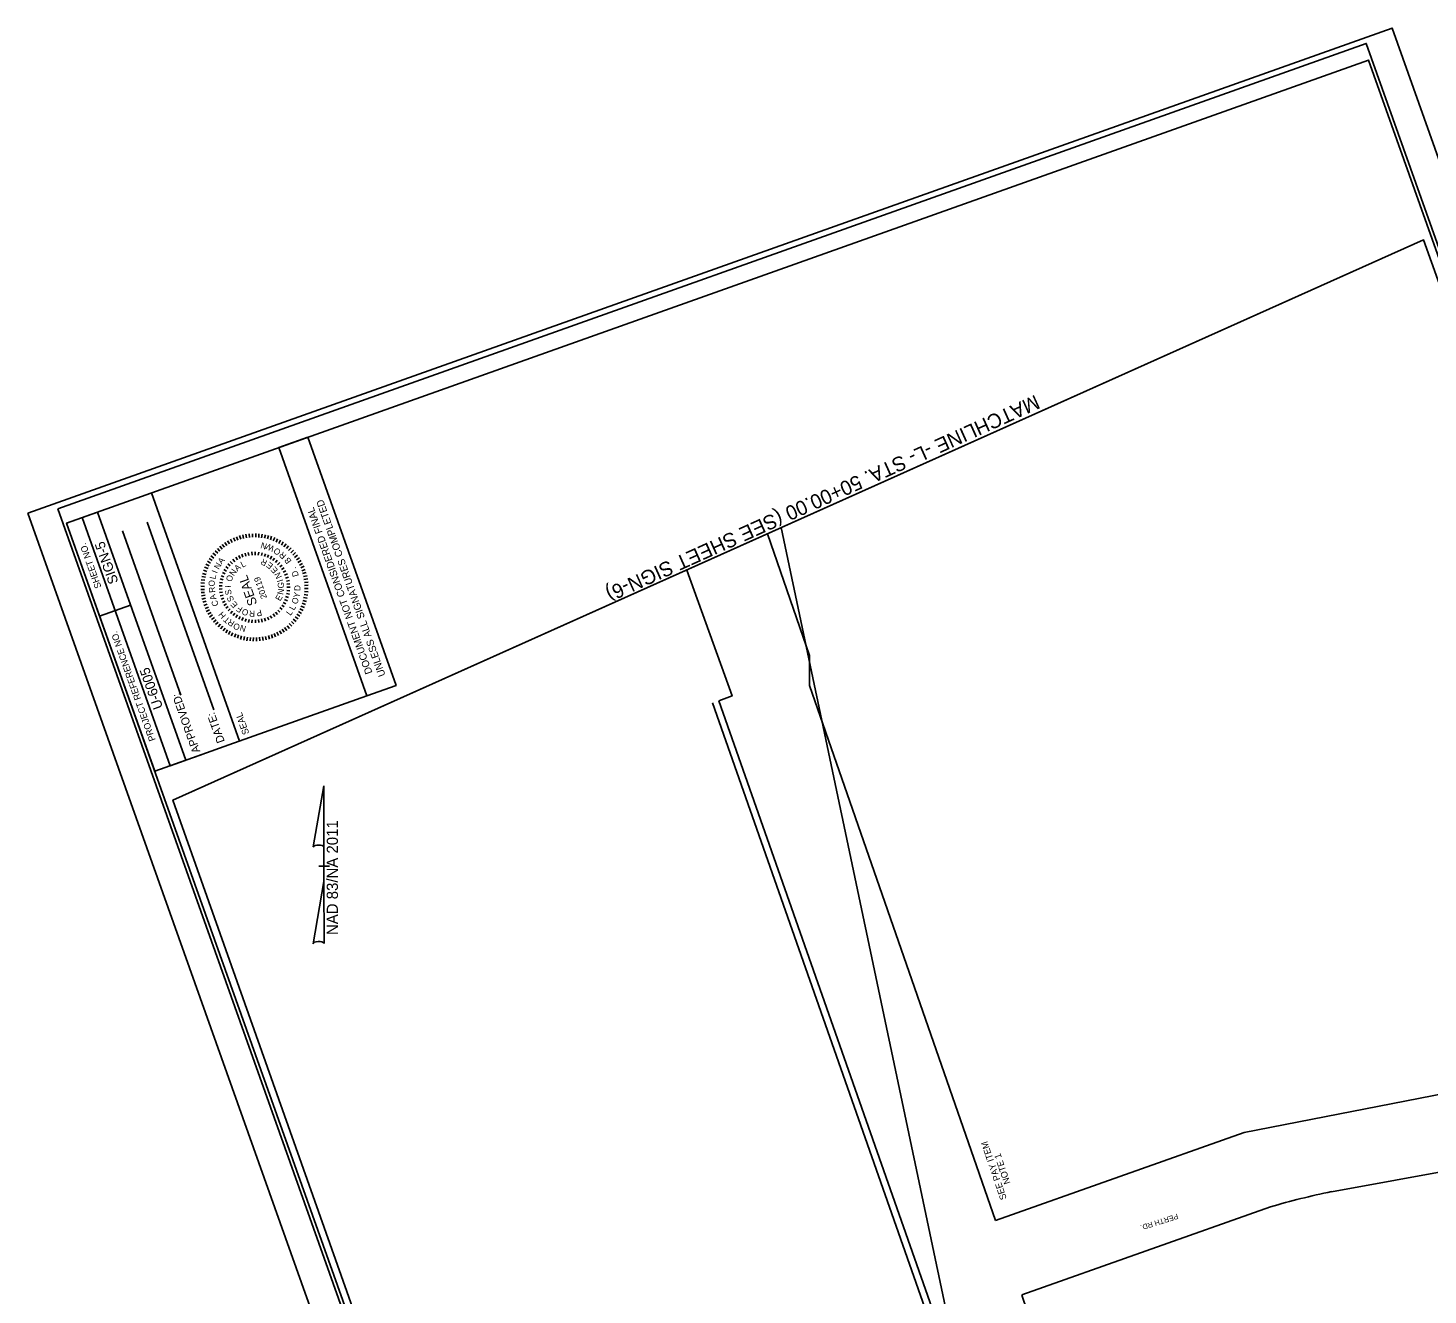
# Model space of a CAD drawing. Extents: x 1615843 to 1617444, y 901966 to 903921.
# Drawn here: x 1615843 to 1616907, y 902958 to 903921 of the extents above; entities that cross this region are included whole.
import ezdxf

# ---------------------------------------------------------------- set-up
doc = ezdxf.new("R2010")
doc.units = 0
for name, color, linetype in [('CTL Primary Horizontal and Vertical CELL', 7, 'Continuous'), ('CTL Primary Horizontal and Vertical Cogo Number', 7, 'Continuous'), ('CTL Secondary Horizontal and Vertical CELL', 7, 'Continuous'), ('CTL Secondary Horizontal and Vertical Cogo Number', 7, 'Continuous'), ('CTL Vertical Benchmark CELL', 7, 'Continuous'), ('Default', 7, 'Continuous'), ('Exist DTM Crownline Cogo Number', 7, 'Continuous'), ('Exist DTM Crownline Cogo Point CELL', 7, 'Continuous'), ('Exist DTM Regular Point CELL', 7, 'Continuous'), ('Exist DTM Regular Point Cogo Number', 7, 'Continuous'), ('Exist Roads Curbs Cogo Number', 7, 'Continuous'), ('Exist Roads Curbs Cogo Point CELL', 7, 'Continuous'), ('Exist Roads EOP Cogo Number', 7, 'Continuous'), ('Exist Roads EOT Cogo Number', 7, 'Continuous'), ('Exist Structure Minor Pipes RCP 15 Inch Cogo Number', 7, 'Continuous'), ('Exist Structure Minor Pipes RCP 15 Inch Cogo Point CELL', 7, 'Continuous')]:
    doc.layers.add(name, color=color, linetype=linetype)

msp = doc.modelspace()

# ---------------------------------------------------------------- linework, layer by layer
at = {"layer": 'CTL Primary Horizontal and Vertical CELL'}
msp.add_lwpolyline([(1615865.7, 903555.7), (1616423.9, 901985.4), (1617418.1, 902338.9), (1616859.8, 903909.1)], close=True, dxfattribs=at)
at = {"layer": 'CTL Primary Horizontal and Vertical Cogo Number'}
msp.add_lwpolyline([(1615843, 903552.4), (1616407.1, 901965.7), (1617443.6, 902334.1), (1616879.5, 903920.8)], close=True, dxfattribs=at)
at = {"layer": 'CTL Secondary Horizontal and Vertical CELL'}
for p, q in [((1615962.9, 903364.6), (1615895.9, 903553.1)), ((1615962.9, 903364.6), (1615895.9, 903553.1)), ((1615951.1, 903360.4), (1615884.1, 903548.9)), ((1615897.4, 903474.1), (1615921, 903482.5)), ((1615962.9, 903364.6), (1615974.7, 903368.8))]:
    msp.add_line(p, q, dxfattribs=at)
for points in [[(1615872.3, 903544.7), (1616374.7, 902131.4), (1617364.1, 902483.1), (1616861.6, 903896.5)], [(1615939.3, 903356.2), (1615872.3, 903544.7), (1615895.9, 903553.1), (1615962.9, 903364.6)]]:
    msp.add_lwpolyline(points, close=True, dxfattribs=at)
at = {"layer": 'Default'}
for p, q in [((1615996.9, 903532.5), (1615998.2, 903530)), ((1615999.2, 903533.5), (1616000.3, 903531)), ((1616001.5, 903534.4), (1616002.4, 903531.8)), ((1616003.8, 903535.2), (1616004.6, 903532.5)), ((1616006.2, 903535.8), (1616006.8, 903533.1)), ((1616008.6, 903536.3), (1616009.1, 903533.5)), ((1616011.1, 903536.6), (1616011.4, 903533.8)), ((1616013.6, 903536.7), (1616013.7, 903534)), ((1616016, 903536.8), (1616016, 903534)), ((1616018.5, 903536.6), (1616018.3, 903533.9)), ((1616020.9, 903536.4), (1616020.5, 903533.6)), ((1616023.4, 903535.9), (1616022.8, 903533.2)), ((1616025.8, 903535.4), (1616025, 903532.7)), ((1616028.1, 903534.7), (1616027.3, 903532)), ((1616030.5, 903533.8), (1616029.4, 903531.2)), ((1616032.7, 903532.8), (1616031.5, 903530.3)), ((1616034.9, 903531.7), (1616033.6, 903529.2)), ((1615983.5, 903521.8), (1615985.7, 903520)), ((1615985.1, 903523.7), (1615987.2, 903521.8)), ((1615986.9, 903525.4), (1615988.8, 903523.4)), ((1615988.7, 903527.1), (1615990.5, 903525)), ((1615990.6, 903528.6), (1615992.3, 903526.4)), ((1615992.6, 903530), (1615994.2, 903527.7)), ((1615994.7, 903531.3), (1615996.1, 903528.9)), ((1616005.5, 903521.1), (1616006.3, 903518.9)), ((1616008, 903521.9), (1616008.6, 903519.6)), ((1616010.8, 903520.1), (1616010.4, 903522.4)), ((1616013.1, 903522.8), (1616013.3, 903520.5)), ((1616015.7, 903522.8), (1616015.7, 903520.5)), ((1616018.3, 903522.6), (1616018, 903520.3)), ((1616020.9, 903522.2), (1616020.4, 903520)), ((1616023.4, 903521.5), (1616022.7, 903519.3)), ((1616037, 903530.4), (1616035.5, 903528.1)), ((1616039.1, 903529), (1616037.4, 903526.8)), ((1616041, 903527.5), (1616039.3, 903525.4)), ((1616042.9, 903525.9), (1616041, 903523.9)), ((1616044.7, 903524.2), (1616042.6, 903522.2)), ((1616046.3, 903522.3), (1616044.2, 903520.5)), ((1615977.2, 903511.2), (1615979.8, 903510.2)), ((1615978.2, 903513.5), (1615980.7, 903512.3)), ((1615979.4, 903515.7), (1615981.8, 903514.3)), ((1615980.6, 903517.8), (1615983, 903516.3)), ((1615982, 903519.8), (1615984.3, 903518.2)), ((1615993.3, 903511.7), (1615995.2, 903510.3)), ((1615994.9, 903513.7), (1615996.7, 903512.2)), ((1615996.7, 903515.6), (1615998.3, 903513.9)), ((1615998.7, 903517.3), (1616000.1, 903515.4)), ((1616000.9, 903518.8), (1616002.1, 903516.8)), ((1616003.1, 903520), (1616004.2, 903517.9)), ((1616025.8, 903520.6), (1616024.9, 903518.5)), ((1616028.2, 903519.5), (1616027, 903517.4)), ((1616030.4, 903518.1), (1616029.1, 903516.2)), ((1616032.4, 903516.5), (1616031, 903514.8)), ((1616034.4, 903514.8), (1616032.7, 903513.1)), ((1616036.1, 903512.8), (1616034.3, 903511.4)), ((1616037.6, 903510.7), (1616035.7, 903509.4)), ((1616047.8, 903520.4), (1616045.6, 903518.7)), ((1616049.3, 903518.4), (1616046.9, 903516.9)), ((1616050.6, 903516.3), (1616048.1, 903514.9)), ((1616051.7, 903514.1), (1616049.2, 903512.9)), ((1616052.8, 903511.9), (1616050.2, 903510.8)), ((1615974.7, 903501.7), (1615977.4, 903501.3)), ((1615975.1, 903504.1), (1615977.8, 903503.6)), ((1615975.7, 903506.5), (1615978.4, 903505.8)), ((1615976.4, 903508.9), (1615979, 903508)), ((1615988.5, 903499.7), (1615990.8, 903499.4)), ((1615989, 903502.3), (1615991.2, 903501.7)), ((1615989.7, 903504.8), (1615991.9, 903504)), ((1615990.7, 903507.2), (1615992.8, 903506.2)), ((1615991.9, 903509.5), (1615993.9, 903508.3)), ((1616039, 903508.5), (1616036.9, 903507.4)), ((1616040.1, 903506.1), (1616037.9, 903505.2)), ((1616040.9, 903503.7), (1616038.7, 903503)), ((1616041.6, 903501.1), (1616039.3, 903500.7)), ((1616053.7, 903509.6), (1616051, 903508.6)), ((1616054.4, 903507.2), (1616051.7, 903506.4)), ((1616055, 903504.8), (1616052.3, 903504.2)), ((1616055.5, 903502.4), (1616052.7, 903501.9)), ((1616055.8, 903499.9), (1616053, 903499.7)), ((1615974.3, 903496.8), (1615977, 903496.7)), ((1615974.3, 903494.3), (1615977.1, 903494.4)), ((1615974.4, 903499.3), (1615977.2, 903499)), ((1615974.5, 903491.9), (1615977.2, 903492.1)), ((1615974.8, 903489.4), (1615977.5, 903489.9)), ((1615988.2, 903497.1), (1615990.5, 903497)), ((1615988.2, 903494.5), (1615990.5, 903494.7)), ((1615988.5, 903491.9), (1615990.8, 903492.3)), ((1615989, 903489.4), (1615991.2, 903490)), ((1616041.6, 903490.8), (1616039.3, 903491.2)), ((1616039.6, 903498.3), (1616041.9, 903498.5)), ((1616041.9, 903493.4), (1616039.6, 903493.6)), ((1616042.1, 903496), (1616039.7, 903496)), ((1616055.6, 903490.1), (1616052.8, 903490.5)), ((1616055.9, 903492.5), (1616053.1, 903492.8)), ((1616056, 903497.5), (1616053.2, 903497.4)), ((1616056, 903495), (1616053.2, 903495.1)), ((1615975.2, 903487), (1615978, 903487.6)), ((1615975.8, 903484.6), (1615978.5, 903485.4)), ((1615976.6, 903482.2), (1615979.2, 903483.2)), ((1615977.5, 903479.9), (1615980.1, 903481)), ((1615978.5, 903477.7), (1615981, 903478.9)), ((1615989.7, 903486.9), (1615991.9, 903487.7)), ((1615991.9, 903487.7), (1615989.7, 903486.9)), ((1615990.7, 903484.5), (1615992.8, 903485.5)), ((1615991.9, 903482.2), (1615993.9, 903483.4)), ((1615993.4, 903480), (1615995.2, 903481.4)), ((1615995, 903478), (1615996.7, 903479.5)), ((1616034.4, 903477.1), (1616032.8, 903478.7)), ((1616036.2, 903479.1), (1616034.4, 903480.5)), ((1616037.7, 903481.2), (1616035.8, 903482.5)), ((1616039, 903483.4), (1616037, 903484.5)), ((1616040.1, 903485.8), (1616037.9, 903486.7)), ((1616041, 903488.3), (1616038.7, 903488.9)), ((1616052, 903478.3), (1616049.5, 903479.5)), ((1616053, 903480.6), (1616050.4, 903481.6)), ((1616053.9, 903482.9), (1616051.2, 903483.8)), ((1616054.6, 903485.3), (1616051.9, 903486)), ((1616055.2, 903487.7), (1616052.4, 903488.2)), ((1615979.7, 903475.5), (1615982.1, 903476.9)), ((1615981, 903473.4), (1615983.3, 903475)), ((1615982.4, 903471.4), (1615984.6, 903473.1)), ((1615983.9, 903469.5), (1615986.1, 903471.3)), ((1615985.6, 903467.6), (1615987.6, 903469.6)), ((1615987.4, 903465.9), (1615989.3, 903467.9)), ((1615996.8, 903476.1), (1615998.4, 903477.8)), ((1615998.8, 903474.5), (1616000.2, 903476.3)), ((1616001, 903473), (1616002.2, 903475)), ((1616003.2, 903471.7), (1616004.3, 903473.8)), ((1616005.6, 903470.7), (1616006.5, 903472.9)), ((1616008.1, 903469.9), (1616008.7, 903472.1)), ((1616010.6, 903469.3), (1616011, 903471.6)), ((1616013.2, 903469), (1616013.4, 903471.3)), ((1616015.8, 903469), (1616015.8, 903471.3)), ((1616018.4, 903469.2), (1616018.2, 903471.5)), ((1616021, 903469.6), (1616020.5, 903471.9)), ((1616023.5, 903470.3), (1616022.8, 903472.5)), ((1616025.9, 903471.2), (1616025, 903473.4)), ((1616028.3, 903472.4), (1616027.1, 903474.4)), ((1616030.5, 903473.8), (1616029.2, 903475.7)), ((1616032.5, 903475.4), (1616031, 903477.1)), ((1616043.4, 903466.4), (1616041.5, 903468.4)), ((1616045.1, 903468.1), (1616043.1, 903470)), ((1616046.7, 903470), (1616044.6, 903471.8)), ((1616048.3, 903472), (1616046, 903473.6)), ((1616049.6, 903474), (1616047.3, 903475.5)), ((1616050.9, 903476.1), (1616048.5, 903477.5)), ((1615989.2, 903464.3), (1615991, 903466.4)), ((1615991.2, 903462.8), (1615992.8, 903465)), ((1615993.2, 903461.4), (1615994.7, 903463.7)), ((1615995.3, 903460.1), (1615996.7, 903462.6)), ((1615997.5, 903459), (1615998.7, 903461.5)), ((1615999.8, 903458), (1616000.8, 903460.6)), ((1616002.1, 903457.2), (1616003, 903459.8)), ((1616004.5, 903456.4), (1616005.2, 903459.1)), ((1616006.9, 903455.9), (1616007.4, 903458.6)), ((1616009.3, 903455.4), (1616009.7, 903458.2)), ((1616011.8, 903455.2), (1616012, 903457.9)), ((1616014.2, 903455), (1616014.3, 903457.8)), ((1616016.7, 903455.1), (1616016.6, 903457.8)), ((1616019.2, 903455.2), (1616018.9, 903458)), ((1616021.6, 903455.5), (1616021.2, 903458.3)), ((1616024, 903456), (1616023.4, 903458.7)), ((1616026.4, 903456.6), (1616025.7, 903459.3)), ((1616028.8, 903457.4), (1616027.9, 903460)), ((1616031.1, 903458.3), (1616030, 903460.8)), ((1616033.3, 903459.3), (1616032.1, 903461.8)), ((1616035.5, 903460.5), (1616034.1, 903462.9)), ((1616037.6, 903461.8), (1616036.1, 903464.1)), ((1616039.6, 903463.2), (1616038, 903465.4)), ((1616041.6, 903464.7), (1616039.8, 903466.8))]:
    msp.add_line(p, q, dxfattribs=at)
at = {"layer": 'Exist DTM Crownline Cogo Point CELL'}
msp.add_lwpolyline([(1616920.6, 902383), (1616299.5, 902356.1), (1615953.1, 903334.3), (1616369.2, 903520.6), (1616903.3, 903759.8), (1617120.2, 903154.3), (1617263.4, 902747.8), (1617083.5, 902390)], close=True, dxfattribs=at)
at = {"layer": 'Exist DTM Regular Point CELL'}
for p, q in [((1616415.3, 903541.3), (1616661.7, 902371.8)), ((1616766.9, 903081.8), (1617077.9, 903142.5)), ((1616766.9, 903081.8), (1616578.2, 903014.9)), ((1616984.3, 903064.3), (1616833.4, 903036.8)), ((1616598.2, 902958.4), (1616787, 903025.2))]:
    msp.add_line(p, q, dxfattribs=at)
for points in [[(1616404.9, 903536.6), (1616436.8, 903444.1), (1616436.9, 903421.3)], [(1616367.9, 903409.8), (1616378, 903413.4), (1616343.5, 903509.1)], [(1616578.2, 903014.9), (1616436.9, 903421.3)], [(1616549.9, 902891), (1616367.9, 903409.8)]]:
    msp.add_lwpolyline(points, dxfattribs=at)
for centre, radius, start, end in [((1616953.7, 902455.6), 593.6, 101.6913, 106.3159), ((1614325.7, 902186.3), 2400, 9.05, 18.7638)]:
    msp.add_arc(centre, radius, start, end, dxfattribs=at)
at = {"layer": 'Exist DTM Regular Point Cogo Number'}
msp.add_lwpolyline([(1616544.6, 902890.9), (1616363.2, 903408.1)], dxfattribs=at)
at = {"layer": 'Exist Roads Curbs Cogo Point CELL'}
msp.add_line((1615953.1, 903334.3), (1616903.3, 903759.8), dxfattribs=at)
at = {"layer": 'Exist Roads EOP Cogo Number'}
for p, q in [((1616059.7, 903298.7), (1616067.9, 903345.1)), ((1616067.9, 903345.1), (1616067.9, 903345.1)), ((1616067.9, 903345.1), (1616067.9, 903345.1)), ((1616067.9, 903345.1), (1616067.9, 903297.3)), ((1616067.9, 903272.5), (1616067.9, 903298.7)), ((1616067.9, 903297.3), (1616067.9, 903298.6)), ((1616067.5, 903284.1), (1616063.9, 903284.1)), ((1616063.9, 903284.1), (1616063.9, 903284.1)), ((1616064, 903284.1), (1616072, 903284.1)), ((1616067.9, 903272.5), (1616059.6, 903225.2)), ((1616068, 903225.4), (1616067.9, 903272.5))]:
    msp.add_line(p, q, dxfattribs=at)
for centre, start_param, end_param in [((1616063.8, 903298.2), 0.216388, 2.908219), ((1616063.8, 903225), 0.201328, 3.141593)]:
    msp.add_ellipse(centre, major_axis=(4.23, -0.03), ratio=0.461098, start_param=start_param, end_param=end_param, dxfattribs=at)
at = {"layer": 'Exist Roads EOT Cogo Number'}
msp.add_lwpolyline([(1616100.5, 903413.6), (1616033.5, 903602.1), (1616055.7, 903609.9), (1616122.7, 903421.4)], close=True, dxfattribs=at)
at = {"layer": 'Exist Structure Minor Pipes RCP 15 Inch Cogo Number'}
for p, q in [((1615984.1, 903403), (1615933.5, 903545.5)), ((1615959.1, 903413.9), (1615914.7, 903538.9))]:
    msp.add_line(p, q, dxfattribs=at)
at = {"layer": 'Exist Structure Minor Pipes RCP 15 Inch Cogo Point CELL'}
for p, q in [((1616033.5, 903602.1), (1616100.5, 903413.6)), ((1616003.8, 903379.2), (1615936.8, 903567.7)), ((1616100.5, 903413.6), (1615995.6, 903376.3)), ((1615995.6, 903376.3), (1615951.1, 903360.4))]:
    msp.add_line(p, q, dxfattribs=at)

# ---------------------------------------------------------------- texts
at = {"layer": 'CTL Secondary Horizontal and Vertical CELL'}
for s, p in [('SHEET NO.', (1615898.9, 903496.1)), ('PROJECT REFERENCE NO.', (1615940, 903380.1))]:
    msp.add_text(s, height=5, rotation=109.5707, dxfattribs=at).set_placement(p)
at = {"layer": 'CTL Secondary Horizontal and Vertical Cogo Number'}
for s, p in [('SIGN-5', (1615911.8, 903500)), ('U-6005', (1615945.7, 903404.8))]:
    msp.add_text(s, height=7.5, rotation=109.5707, dxfattribs=at).set_placement(p)
at = {"layer": 'CTL Vertical Benchmark CELL'}
for s, p in [('APPROVED:', (1615974, 903371.3)), ('DATE:', (1615992.6, 903378.9))]:
    msp.add_text(s, height=6.11, rotation=109.5656, dxfattribs=at).set_placement(p)
at = {"layer": 'Default'}
for s, height, rotation, p in [('N', 4.64, 161.7247, (1616025, 903528.9)), ('W', 4.64, 152.8421, (1616030.7, 903526.8)), ('O', 4.64, 143.9595, (1616035.6, 903523.6)), ('R', 4.64, 135.1368, (1616039.7, 903520.2)), ('N', 4.64, 59.8023, (1615988, 903509.1)), ('A', 4.64, 50.0348, (1615990.2, 903513.2)), ('A', 4.64, 40.6846, (1616002.1, 903507.8)), ('L', 4.64, 25.3883, (1616005.9, 903510.8)), ('R', 4.64, 154.0826, (1616025.2, 903516)), ('E', 4.64, 140.3115, (1616029.7, 903512.9)), ('E', 4.64, 130.3256, (1616033.2, 903509)), ('B', 4.64, 126.1343, (1616043.5, 903515.9)), ('.', 4.64, 113.35, (1616046.9, 903510.2)), ('O', 4.64, 91.8085, (1615985, 903496.7)), ('L', 4.64, 78.6722, (1615985.4, 903501.8)), ('I', 4.64, 69.0968, (1615986.7, 903506.2)), ('O', 4.64, 71.2771, (1615997.6, 903499.8)), ('N', 4.64, 55.9808, (1615999.4, 903504.2)), ('SEAL', 6.97, 109.5177, (1616017.3, 903483.4)), ('20119', 4.64, 109.5177, (1616024.7, 903488.1)), ('N', 4.64, 114.9335, (1616036.1, 903503.8)), ('I', 4.64, 107.3039, (1616037, 903500.8)), ('D', 4.64, 105.6076, (1616048.8, 903504.7)), ('R', 4.64, 94.8653, (1615985.3, 903492)), ('A', 4.64, 106.8746, (1615986.3, 903487.1)), ('I', 4.64, 86.5733, (1615997.2, 903495.6)), ('S', 4.64, 101.8695, (1615997.9, 903490.6)), ('S', 4.64, 117.1658, (1615999.8, 903486.4)), ('E', 4.64, 59.5878, (1616034.6, 903485.1)), ('N', 4.64, 80.4428, (1616036.9, 903490.1)), ('G', 4.64, 89.2091, (1616037.4, 903495.1)), ('Y', 4.64, 78.8398, (1616049.1, 903487.7)), ('D', 4.64, 87.8123, (1616049.9, 903493.1)), ('C', 4.64, 106.8746, (1615987.9, 903482.3)), ('E', 4.64, 132.462, (1616002.7, 903482.8)), ('F', 4.64, 147.7583, (1616006.5, 903480.2)), ('O', 4.64, 163.0545, (1616011, 903478.5)), ('P', 4.64, 193.647, (1616020.1, 903479.1)), ('L', 4.64, 61.5245, (1616045.2, 903478.1)), ('O', 4.64, 70.1672, (1616047.4, 903482.7)), ('H', 4.64, 130.5853, (1615993.8, 903474.6)), ('T', 4.64, 140.0173, (1615996.9, 903471.7)), ('R', 4.64, 148.1782, (1616000.4, 903469.7)), ('O', 4.64, 161.235, (1616004.5, 903467.5)), ('R', 4.64, 178.3508, (1616015.5, 903478.2)), ('L', 4.64, 53.4527, (1616042.4, 903474.1)), ('N', 4.64, 163.1944, (1616009.1, 903466.3)), ('SEE PAY ITEM', 5, 108.7793, (1616586.7, 903031.6)), ('NOTE 1', 5, 108.7793, (1616589.5, 903043.5))]:
    msp.add_text(s, height=height, rotation=rotation, dxfattribs=at).set_placement(p)
at = {"layer": 'Exist DTM Crownline Cogo Number'}
msp.add_text('PERTH RD.', height=4, rotation=197.4728, dxfattribs=at).set_placement((1616716.2, 903020.2))
at = {"layer": 'Exist Roads Curbs Cogo Number'}
msp.add_text('MATCHLINE -L- STA. 50+00.00 (SEE SHEET SIGN-6)', height=11, rotation=204.2818, dxfattribs=at).set_placement((1616608.4, 903642.5))
at = {"layer": 'Exist Roads EOP Cogo Number'}
msp.add_text('NAD 83/NA 2011', height=8.5, rotation=90, dxfattribs=at).set_placement((1616078.5, 903231.8))
at = {"layer": 'Exist Roads EOT Cogo Number'}
for s, p in [('DOCUMENT NOT CONSIDERED FINAL', (1616104.8, 903431.1)), ('UNLESS ALL SIGNATURES COMPLETED', (1616114.7, 903429.2))]:
    msp.add_text(s, height=5.498, rotation=109.5707, dxfattribs=at).set_placement(p)
at = {"layer": 'Exist Structure Minor Pipes RCP 15 Inch Cogo Number'}
msp.add_text('SEAL', height=5.09, rotation=109.5656, dxfattribs=at).set_placement((1616011.2, 903385))

doc.saveas('drawing.dxf')
